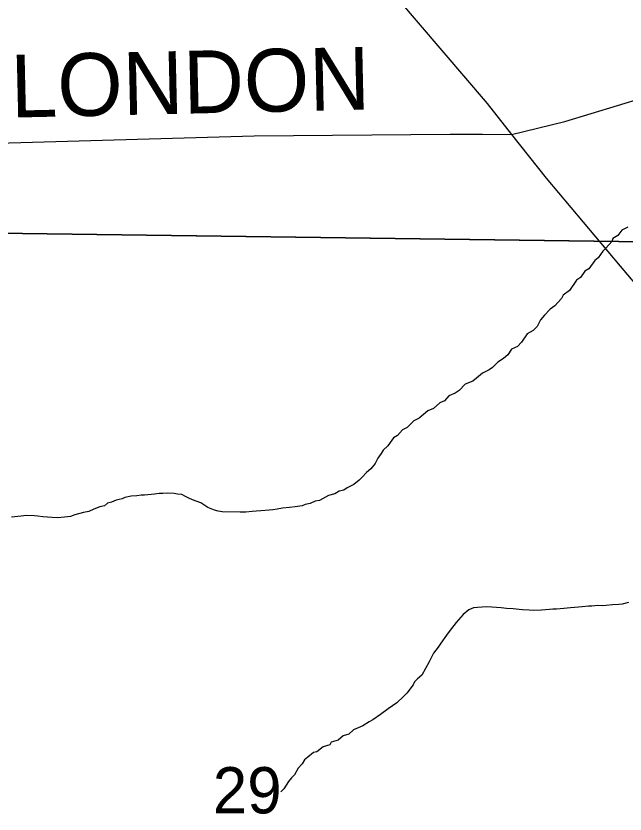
# Model space of a CAD drawing. Extents: x 0 to 34, y -2.3 to 22.
# Drawn here: x 3.675 to 4.226, y 15.878 to 16.601 of the extents above; entities that cross this region are included whole.
import ezdxf

# ---------------------------------------------------------------- set-up
doc = ezdxf.new("R2010")
doc.units = 0
for name, color, linetype in [('GM_X_County_Road', 7, 'Continuous'), ('GM_X_County_Road_Text', 7, 'Continuous'), ('GM_X_Minor_River', 7, 'Continuous'), ('GM_X_Section', 7, 'Continuous'), ('GM_X_Section_Text', 7, 'Continuous')]:
    doc.layers.add(name, color=color, linetype=linetype)

msp = doc.modelspace()

# ---------------------------------------------------------------- linework, layer by layer
at = {"layer": 'GM_X_County_Road'}
for p, q in [((3.9851, 16.65726), (4.10129, 16.52135)), ((4.17143, 16.50489), (4.25979, 16.53214)), ((4.10129, 16.52135), (4.12335, 16.49321)), ((4.12335, 16.49321), (4.17143, 16.50489)), ((3.8905, 16.49216), (4.06773, 16.49368)), ((4.06773, 16.49368), (4.09682, 16.4935)), ((4.09682, 16.4935), (4.12335, 16.49321)), ((4.12335, 16.49321), (4.12335, 16.49321)), ((4.12335, 16.49321), (4.15462, 16.45361)), ((3.64337, 16.48492), (3.8905, 16.49216)), ((4.15462, 16.45361), (4.22166, 16.37393)), ((4.22166, 16.37393), (4.27308, 16.31263))]:
    msp.add_line(p, q, dxfattribs=at)
at = {"layer": 'GM_X_Minor_River'}
for p, q in [((4.223, 16.40653), (4.21943, 16.40169)), ((4.2284, 16.4094), (4.223, 16.40653)), ((4.2148, 16.39917), (4.21396, 16.39654)), ((4.21943, 16.40169), (4.2148, 16.39917)), ((4.21396, 16.39654), (4.20885, 16.39061)), ((4.20572, 16.38767), (4.20175, 16.38171)), ((4.20885, 16.39061), (4.20572, 16.38767)), ((4.19864, 16.37914), (4.1931, 16.37171)), ((4.20175, 16.38171), (4.19864, 16.37914)), ((4.1931, 16.37171), (4.18961, 16.36953)), ((4.18565, 16.36395), (4.18215, 16.3614)), ((4.18961, 16.36953), (4.18565, 16.36395)), ((4.18215, 16.3614), (4.1758, 16.35209)), ((4.1758, 16.35209), (4.16997, 16.34771)), ((4.16836, 16.34472), (4.16247, 16.33806)), ((4.16997, 16.34771), (4.16836, 16.34472)), ((4.1582, 16.33514), (4.1531, 16.3296)), ((4.16247, 16.33806), (4.1582, 16.33514)), ((4.1531, 16.3296), (4.14956, 16.32552)), ((4.14635, 16.31954), (4.14282, 16.31585)), ((4.14956, 16.32552), (4.14635, 16.31954)), ((4.13742, 16.31297), (4.13225, 16.30515)), ((4.14282, 16.31585), (4.13742, 16.31297)), ((4.13225, 16.30515), (4.12872, 16.30146)), ((4.12332, 16.29896), (4.11975, 16.29375)), ((4.12872, 16.30146), (4.12332, 16.29896)), ((4.11975, 16.29375), (4.11585, 16.29044)), ((4.11082, 16.28717), (4.10612, 16.28238)), ((4.11585, 16.29044), (4.11082, 16.28717)), ((4.09685, 16.27733), (4.09139, 16.27256)), ((4.10301, 16.28019), (4.09685, 16.27733)), ((4.10612, 16.28238), (4.10301, 16.28019)), ((4.08827, 16.26999), (4.08135, 16.26716)), ((4.09139, 16.27256), (4.08827, 16.26999)), ((4.08135, 16.26716), (4.07587, 16.26162)), ((4.0666, 16.25658), (4.06267, 16.25214)), ((4.07237, 16.25907), (4.0666, 16.25658)), ((4.07587, 16.26162), (4.07237, 16.25907)), ((4.05843, 16.25037), (4.05258, 16.24523)), ((4.06267, 16.25214), (4.05843, 16.25037)), ((4.04758, 16.2431), (4.03978, 16.23649)), ((4.05258, 16.24523), (4.04758, 16.2431)), ((4.03477, 16.23398), (4.0289, 16.22808)), ((4.03978, 16.23649), (4.03477, 16.23398)), ((4.02465, 16.22592), (4.01994, 16.22075)), ((4.0289, 16.22808), (4.02465, 16.22592)), ((4.01646, 16.21857), (4.01131, 16.21151)), ((4.01994, 16.22075), (4.01646, 16.21857)), ((4.01131, 16.21151), (4.00701, 16.20746)), ((4.0054, 16.20447), (4.00225, 16.20038)), ((4.00701, 16.20746), (4.0054, 16.20447)), ((4.00225, 16.20038), (3.99982, 16.19552)), ((3.99588, 16.1907), (3.99198, 16.18739)), ((3.99982, 16.19552), (3.99588, 16.1907)), ((3.98806, 16.18295), (3.98532, 16.18037)), ((3.99198, 16.18739), (3.98806, 16.18295)), ((3.98064, 16.17633), (3.97448, 16.17348)), ((3.98532, 16.18037), (3.98064, 16.17633)), ((3.80441, 16.1683), (3.80021, 16.16766)), ((3.80783, 16.1682), (3.80441, 16.1683)), ((3.81164, 16.16846), (3.80783, 16.1682)), ((3.8181, 16.16827), (3.81164, 16.16846)), ((3.82112, 16.1678), (3.8181, 16.16827)), ((3.82491, 16.16731), (3.82112, 16.1678)), ((3.9633, 16.16812), (3.95754, 16.16639)), ((3.96716, 16.17028), (3.9633, 16.16812)), ((3.97137, 16.17129), (3.96716, 16.17028)), ((3.97448, 16.17348), (3.97137, 16.17129)), ((3.76547, 16.16224), (3.76123, 16.16047)), ((3.77083, 16.1636), (3.76547, 16.16224)), ((3.77352, 16.16466), (3.77083, 16.1636)), ((3.77926, 16.16601), (3.77352, 16.16466)), ((3.78421, 16.16624), (3.77926, 16.16601)), ((3.78803, 16.16689), (3.78421, 16.16624)), ((3.79107, 16.1668), (3.78803, 16.16689)), ((3.79717, 16.16738), (3.79107, 16.1668)), ((3.80021, 16.16766), (3.79717, 16.16738)), ((3.82828, 16.16569), (3.82491, 16.16731)), ((3.83128, 16.16408), (3.82828, 16.16569)), ((3.83465, 16.16246), (3.83128, 16.16408)), ((3.84218, 16.15995), (3.83465, 16.16246)), ((3.94562, 16.16142), (3.94099, 16.15928)), ((3.94944, 16.16207), (3.94562, 16.16142)), ((3.95754, 16.16639), (3.94944, 16.16207)), ((3.74546, 16.1541), (3.74084, 16.15196)), ((3.75085, 16.15622), (3.74546, 16.1541)), ((3.75506, 16.15723), (3.75085, 16.15622)), ((3.75778, 16.15943), (3.75506, 16.15723)), ((3.76123, 16.16047), (3.75778, 16.15943)), ((3.84852, 16.15558), (3.84218, 16.15995)), ((3.85453, 16.15313), (3.84852, 16.15558)), ((3.90738, 16.15345), (3.90395, 16.15317)), ((3.9112, 16.1541), (3.90738, 16.15345)), ((3.91616, 16.15509), (3.9112, 16.1541)), ((3.92226, 16.15566), (3.91616, 16.15509)), ((3.9276, 16.15627), (3.92226, 16.15566)), ((3.93371, 16.15722), (3.9276, 16.15627)), ((3.9364, 16.15828), (3.93371, 16.15722)), ((3.94099, 16.15928), (3.9364, 16.15828)), ((3.67952, 16.14771), (3.67075, 16.14683)), ((3.68448, 16.14832), (3.67952, 16.14771)), ((3.69169, 16.14811), (3.68448, 16.14832)), ((3.69472, 16.14764), (3.69169, 16.14811)), ((3.69927, 16.14712), (3.69472, 16.14764)), ((3.70761, 16.1465), (3.69927, 16.14712)), ((3.71255, 16.14635), (3.70761, 16.1465)), ((3.71865, 16.14692), (3.71255, 16.14635)), ((3.72437, 16.14751), (3.71865, 16.14692)), ((3.72821, 16.14892), (3.72437, 16.14751)), ((3.73587, 16.15097), (3.72821, 16.14892)), ((3.74084, 16.15196), (3.73587, 16.15097)), ((3.85793, 16.15226), (3.85453, 16.15313)), ((3.86133, 16.15178), (3.85793, 16.15226)), ((3.87766, 16.1513), (3.86133, 16.15178)), ((3.88299, 16.15152), (3.87766, 16.1513)), ((3.88871, 16.15211), (3.88299, 16.15152)), ((3.89214, 16.15239), (3.88871, 16.15211)), ((3.89633, 16.15264), (3.89214, 16.15239)), ((3.90395, 16.15317), (3.89633, 16.15264)), ((4.20135, 16.0668), (4.19601, 16.0662)), ((4.2059, 16.06666), (4.20135, 16.0668)), ((4.20895, 16.06695), (4.2059, 16.06666)), ((4.21467, 16.06754), (4.20895, 16.06695)), ((4.22038, 16.06775), (4.21467, 16.06754)), ((4.22343, 16.06804), (4.22038, 16.06775)), ((4.22918, 16.06976), (4.22343, 16.06804)), ((4.08454, 16.06307), (4.07948, 16.05866)), ((4.08878, 16.06484), (4.08454, 16.06307)), ((4.09259, 16.0651), (4.08878, 16.06484)), ((4.10096, 16.06562), (4.09259, 16.0651)), ((4.10552, 16.06548), (4.10096, 16.06562)), ((4.11386, 16.06485), (4.10552, 16.06548)), ((4.11879, 16.06432), (4.11386, 16.06485)), ((4.12486, 16.06376), (4.11879, 16.06432)), ((4.13016, 16.06322), (4.12486, 16.06376)), ((4.1332, 16.06313), (4.13016, 16.06322)), ((4.13927, 16.06257), (4.1332, 16.06313)), ((4.14306, 16.06246), (4.13927, 16.06257)), ((4.15029, 16.06262), (4.14306, 16.06246)), ((4.15753, 16.06317), (4.15029, 16.06262)), ((4.16058, 16.06346), (4.15753, 16.06317)), ((4.16401, 16.06373), (4.16058, 16.06346)), ((4.17048, 16.0643), (4.16401, 16.06373)), ((4.17658, 16.06488), (4.17048, 16.0643)), ((4.18382, 16.06542), (4.17658, 16.06488)), ((4.18725, 16.0657), (4.18382, 16.06542)), ((4.19297, 16.06629), (4.18725, 16.0657)), ((4.19601, 16.0662), (4.19297, 16.06629)), ((4.07948, 16.05866), (4.07319, 16.05163)), ((4.07319, 16.05163), (4.06687, 16.04346)), ((4.06449, 16.04011), (4.05934, 16.03267)), ((4.06687, 16.04346), (4.06449, 16.04011)), ((4.05934, 16.03267), (4.05696, 16.02932)), ((4.05261, 16.02375), (4.04859, 16.01589)), ((4.05696, 16.02932), (4.05261, 16.02375)), ((4.04859, 16.01589), (4.04216, 16.00393)), ((4.04216, 16.00393), (4.03826, 16.00063)), ((4.0343, 15.99505), (4.02838, 15.98763)), ((4.03551, 15.99767), (4.0343, 15.99505)), ((4.03826, 16.00063), (4.03551, 15.99767)), ((4.02838, 15.98763), (4.02564, 15.98467)), ((4.02564, 15.98467), (4.01938, 15.97878)), ((4.01162, 15.97331), (4.00463, 15.9682)), ((4.01938, 15.97878), (4.01162, 15.97331)), ((4.00463, 15.9682), (3.99765, 15.96347)), ((3.99456, 15.96166), (3.98875, 15.95804)), ((3.99765, 15.96347), (3.99456, 15.96166)), ((3.98028, 15.95449), (3.97599, 15.95044)), ((3.98875, 15.95804), (3.98028, 15.95449)), ((3.96633, 15.94503), (3.9602, 15.94332)), ((3.97101, 15.94907), (3.96633, 15.94503)), ((3.97599, 15.95044), (3.97101, 15.94907)), ((3.95285, 15.93898), (3.94702, 15.93459)), ((3.95898, 15.94069), (3.95285, 15.93898)), ((3.9602, 15.94332), (3.95898, 15.94069)), ((3.93889, 15.92951), (3.93579, 15.92733)), ((3.94396, 15.93392), (3.93889, 15.92951)), ((3.94702, 15.93459), (3.94396, 15.93392)), ((3.93378, 15.92359), (3.93024, 15.91952)), ((3.93579, 15.92733), (3.93378, 15.92359)), ((3.93024, 15.91952), (3.92702, 15.91353)), ((3.92429, 15.91096), (3.92153, 15.90762)), ((3.92702, 15.91353), (3.92429, 15.91096)), ((3.91715, 15.90091), (3.91442, 15.89833)), ((3.92153, 15.90762), (3.91715, 15.90091))]:
    msp.add_line(p, q, dxfattribs=at)
at = {"layer": 'GM_X_Section'}
for p, q in [((4.31696, 16.39529), (3.51408, 16.40568)), ((3.51408, 16.40568), (4.31696, 16.39529))]:
    msp.add_line(p, q, dxfattribs=at)

# ---------------------------------------------------------------- texts
at = {"layer": 'GM_X_County_Road_Text'}
msp.add_text('LONDON', height=0.056818, rotation=1.30148, dxfattribs=at).set_placement((3.67066, 16.50852))
at = {"layer": 'GM_X_Section_Text'}
msp.add_text('29', height=0.041856, rotation=0.00001, dxfattribs=at).set_placement((3.85298, 15.87874))

doc.saveas('drawing.dxf')
